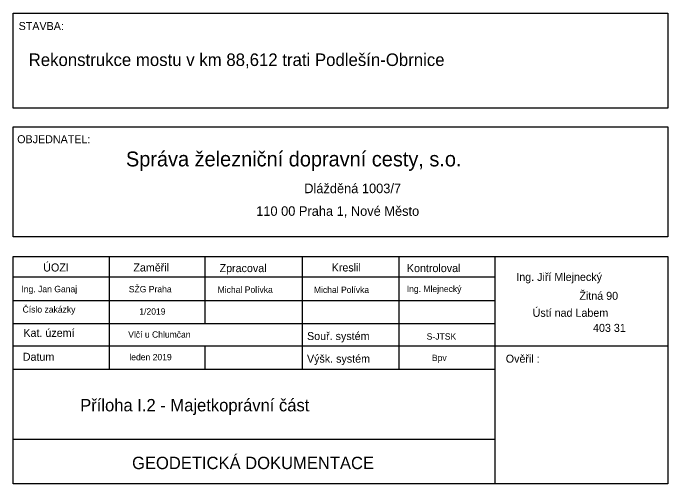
# Model space of a CAD drawing. Extents: x -879530 to -879371, y -1019242 to -1019127.
import ezdxf

# ---------------------------------------------------------------- set-up
doc = ezdxf.new("R2010")
doc.units = 0
doc.layers.add('LEGENDA', color=7, linetype='Continuous')
doc.layers.add('tabulka', color=7, linetype='Continuous')

msp = doc.modelspace()

# ---------------------------------------------------------------- linework, layer by layer
at = {"layer": 'tabulka'}
for p, q in [((-879530.09, -1019186.45), (-879371.44, -1019186.45)), ((-879506.8, -1019186.45), (-879506.8, -1019213.77)), ((-879483.66, -1019186.45), (-879483.66, -1019202.65)), ((-879460.06, -1019186.45), (-879460.06, -1019213.77)), ((-879436.61, -1019186.45), (-879436.61, -1019213.77)), ((-879413.31, -1019241.58), (-879413.31, -1019186.45)), ((-879530.09, -1019191.36), (-879413.31, -1019191.36)), ((-879530.09, -1019197.07), (-879413.31, -1019197.07)), ((-879530.09, -1019202.65), (-879413.31, -1019202.65)), ((-879530.09, -1019208.07), (-879371.44, -1019208.07)), ((-879483.66, -1019208.07), (-879483.66, -1019213.77)), ((-879530.09, -1019213.77), (-879413.31, -1019213.77)), ((-879530.09, -1019230.76), (-879413.31, -1019230.76))]:
    msp.add_line(p, q, dxfattribs=at)
for points in [[(-879530.09, -1019127.36), (-879371.44, -1019127.36), (-879371.44, -1019150.43), (-879530.09, -1019150.43)], [(-879530.09, -1019154.95), (-879371.44, -1019154.95), (-879371.44, -1019181.64), (-879530.09, -1019181.64)]]:
    msp.add_lwpolyline(points, close=True, dxfattribs=at)
msp.add_lwpolyline([(-879371.44, -1019186.45), (-879371.44, -1019241.58), (-879530.09, -1019241.58), (-879530.09, -1019186.45)], dxfattribs=at)

# ---------------------------------------------------------------- texts
at = {"layer": 'LEGENDA'}
msp.add_text('Rekonstrukce mostu v km 88,612 trati Podlešín-Obrnice', height=3.04, dxfattribs=at).set_placement((-879526.32, -1019140.2))
at = {"layer": 'tabulka'}
for s, height, p in [('STAVBA:', 1.94, (-879528.75, -1019131.47)), ('OBJEDNATEL:', 1.94, (-879529.1, -1019158.93)), ('Správa železniční dopravní cesty, s.o.', 3.61, (-879502.75, -1019164.56)), ('Dlážděná 1003/7', 2.32, (-879459.55, -1019171.05)), ('110 00 Praha 1, Nové Město', 2.32, (-879471.19, -1019176.55)), ('ÚOZI', 1.94, (-879522.79, -1019190.05)), ('Zaměřil', 1.94, (-879500.95, -1019190.05)), ('Zpracoval', 1.94, (-879480.06, -1019190.2)), ('Kreslil', 1.94, (-879452.9, -1019190.05)), ('Kontroloval', 1.94, (-879434.68, -1019190.2)), ('Ing. Jiří Mlejnecký', 1.94, (-879408.17, -1019192.34)), ('Ing. Jan Ganaj', 1.552, (-879528.08, -1019195.08)), ('SŽG Praha', 1.552, (-879502.06, -1019195.11)), ('Ing. Mlejnecký', 1.552, (-879434.72, -1019195.04)), ('Michal Polívka', 1.552, (-879480.54, -1019195.23)), ('Michal Polívka', 1.552, (-879457.21, -1019195.27)), ('Žitná 90', 1.94, (-879392.88, -1019196.92)), ('Číslo zakázky', 1.552, (-879527.79, -1019200.03)), ('1/2019', 1.552, (-879499.51, -1019200.52)), ('Ústí nad Labem', 1.94, (-879404.21, -1019201.04)), ('403 31', 1.94, (-879389.58, -1019204.7)), ('Kat. území', 1.94, (-879527.6, -1019205.91)), ('Vlčí u Chlumčan', 1.552, (-879502.2, -1019206.11)), ('Souř. systém', 1.94, (-879458.87, -1019206.68)), ('S-JTSK', 1.552, (-879429.88, -1019206.59)), ('Datum', 1.94, (-879527.74, -1019211.71)), ('leden 2019', 1.552, (-879501.93, -1019211.6)), ('Výšk. systém', 1.94, (-879458.89, -1019212.17)), ('Bpv', 1.552, (-879428.62, -1019211.78)), ('Ověřil :', 1.94, (-879410.72, -1019212.17)), ('Příloha I.2 - Majetkoprávní část', 3, (-879513.83, -1019223.98)), ('GEODETICKÁ DOKUMENTACE ', 3, (-879501.27, -1019237.99))]:
    msp.add_text(s, height=height, dxfattribs=at).set_placement(p)

doc.saveas('drawing.dxf')
